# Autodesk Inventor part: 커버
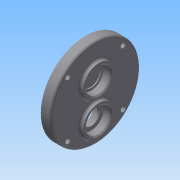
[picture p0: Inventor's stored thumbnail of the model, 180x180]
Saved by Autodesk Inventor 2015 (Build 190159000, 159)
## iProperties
Created: 2015-06
Part Number: 커버
Material: 일반
Document SubType Name: Modeling
Designer: AMC
Density: 1 g/cm^3
Appearance: 기본값
Author: AMC
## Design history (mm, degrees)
sketch "스케치1"
  geometry: C1 r 40 at (0, 0); 1 further point
  constraints: 1 centre point, 1 coincident
  dimensions: "d0" = 80 diameter of C1
extrude "돌출1" new body sketch "스케치1" distance "d1" = 9; taper "d2" = 0 deg
sketch "스케치3"
  geometry: C1 r 14 at (0, 11); C2 r 14 at (0, -20); 1 further point
  constraints: 2 centre point
  dimensions: "d6" = 28 diameter of C1; "d7" = 28 diameter of C2; "d8" = 11 distance of point (0, 0) C1.centre; "d9" = 20 distance of C2.centre point (0, 0)
extrude "돌출3" join sketch "스케치3" distance "d10" = 3; taper "d11" = 0 deg
sketch "스케치4"
  geometry: C1 r 15 at (0, -20); 1 further point
  constraints: 1 centre point
  dimensions: "d12" = 30 diameter of C1; "d13" = 20 distance of C1.centre point (0, 0)
extrude "돌출4" join sketch "스케치4" distance "d14" = 4; taper "d15" = 0 deg
sketch "스케치5"
  geometry: C1 r 14 at (0, 31) reference; C2 r 14 at (0, 0) reference; 2 further points
  constraints: 1 coincident
hole "구멍1" sketch "스케치5" at (0, 0) diameter "d16" = 15; stored, may be unused: countersink angle "d20" = 90 deg, drill point angle "d22" = 118 deg; dims "d17" = 6, "d18" = 22, "d19" = 7, "d21" = 8
sketch "스케치6"
  geometry: C1 r 7.5 at (0, 0) reference; C2 r 11 at (0, 0); 1 further point
  constraints: 1 centre point, 1 coincident
  dimensions: "d23" = 22 diameter of C2
extrude "돌출5" cut sketch "스케치6" distance "d24" = 7; taper "d25" = 0 deg
sketch "스케치7"
  geometry: C1 r 11 at (0, 0); 1 further point
  constraints: 1 centre point
  dimensions: "d26" = 22 diameter of C1
extrude "돌출6" cut sketch "스케치7" distance "d27" = 7; taper "d28" = 0 deg
sketch "스케치8"
  geometry: C1 r 11 at (0, -31) reference; C2 r 7.5 at (0, -31) reference; C3 r 40 at (0, -11) reference; C4 r 9 at (0, 0); 2 further points
  constraints: 1 centre point, 1 coincident, 1 vertical alignment
  dimensions: "d29" = 18 diameter of C4
extrude "돌출7" cut sketch "스케치8" distance "d30" = 1; taper "d31" = 0 deg
fillet "모깎기1" dims "d32" = 0.3
fillet "모깎기2" dims "d33" = 2
chamfer "모따기1" distance "d34" = 1; stored, may be unused: second distance "d35" = 2, angle "d36" = 45 deg
sketch "스케치9" dims "d37" = 70
  geometry: L1 (0, 0)-(40.919, 40.919); L2 (0, 0)-(57.868, 0); 2 further points
  constraints: 4 end point, 1 coincident, 1 equal length, 1 horizontal, 1 point on line, 3 other
  dimensions: "d38" = 45 deg angle of L2 L1
hole "구멍2" sketch "스케치9" at (24.749, 24.749) diameter "d39" = 4.5; stored, may be unused: countersink angle "d43" = 90 deg, drill point angle "d45" = 118 deg; dims "d40" = 6, "d41" = 8, "d42" = 4.4, "d44" = 8
node "솔리드1"
pattern_circular "원형 패턴1" dims angle "d47" = 360 deg
node "절단 모서리 투영1"
node "절단 모서리 투영2"
